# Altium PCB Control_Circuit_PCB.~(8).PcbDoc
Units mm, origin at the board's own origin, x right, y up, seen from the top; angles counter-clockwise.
Board outline 151.39 x 92 mm, 2 copper layers (Top Layer, Bottom Layer); 9 components, 6 nets, 22 pads, 1 vias.
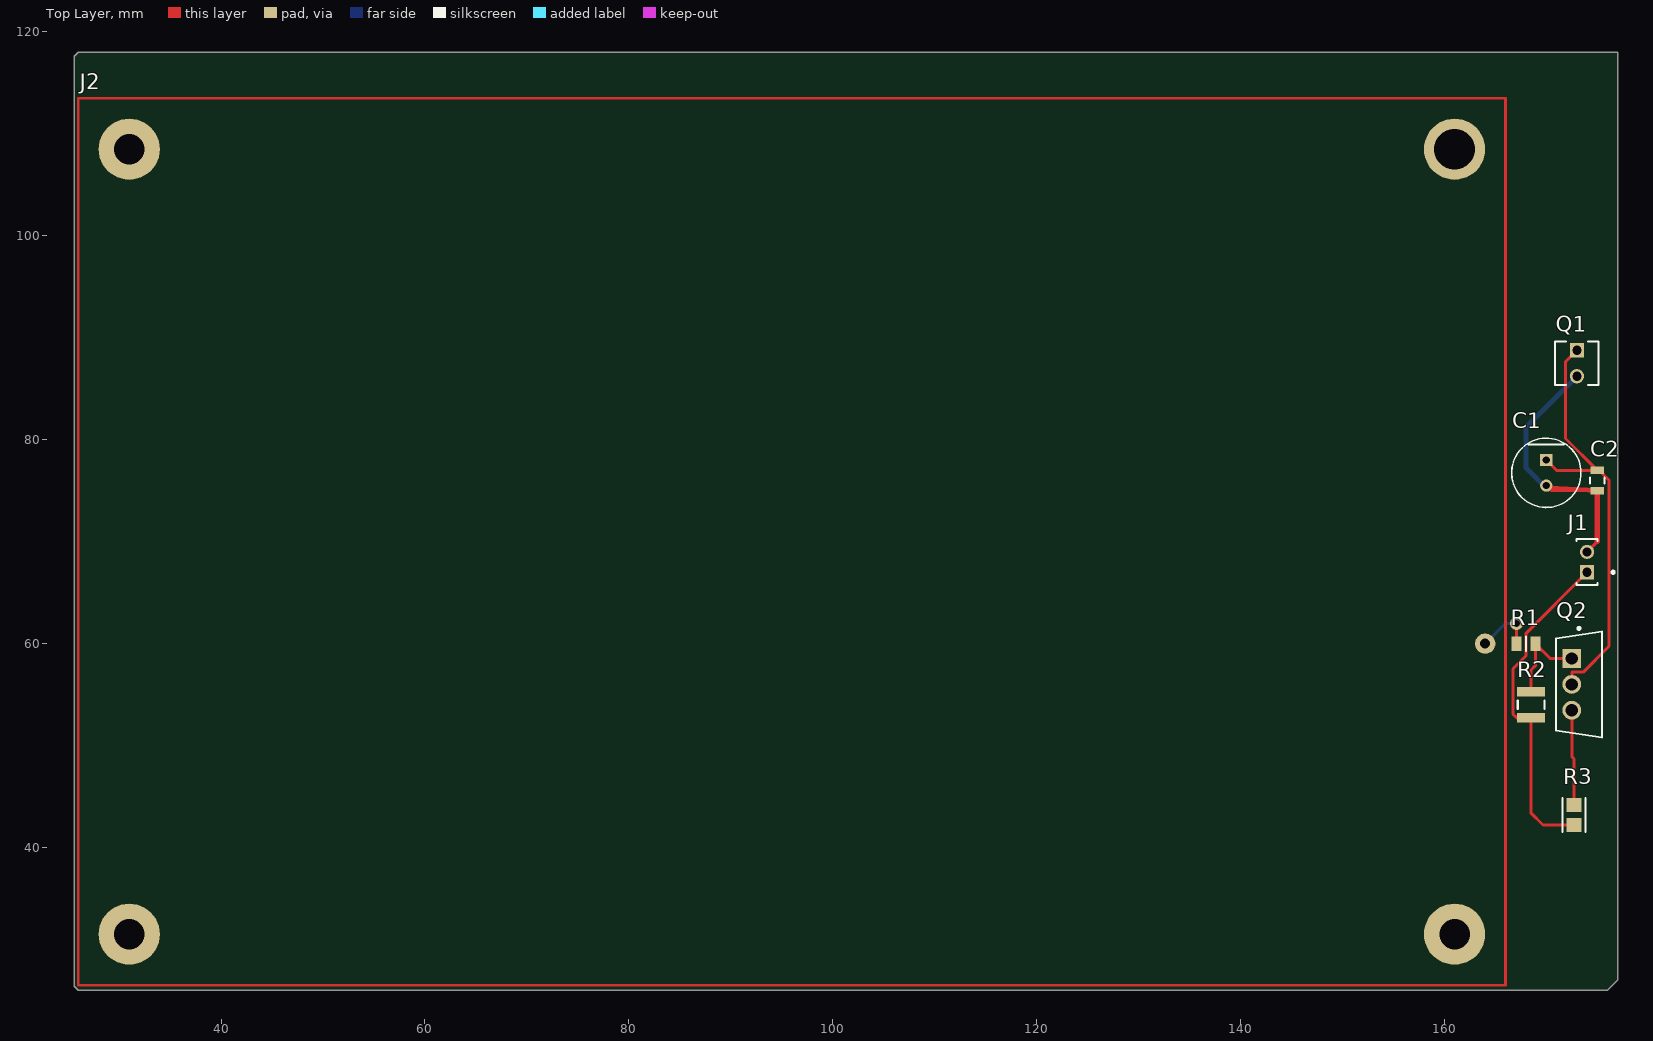
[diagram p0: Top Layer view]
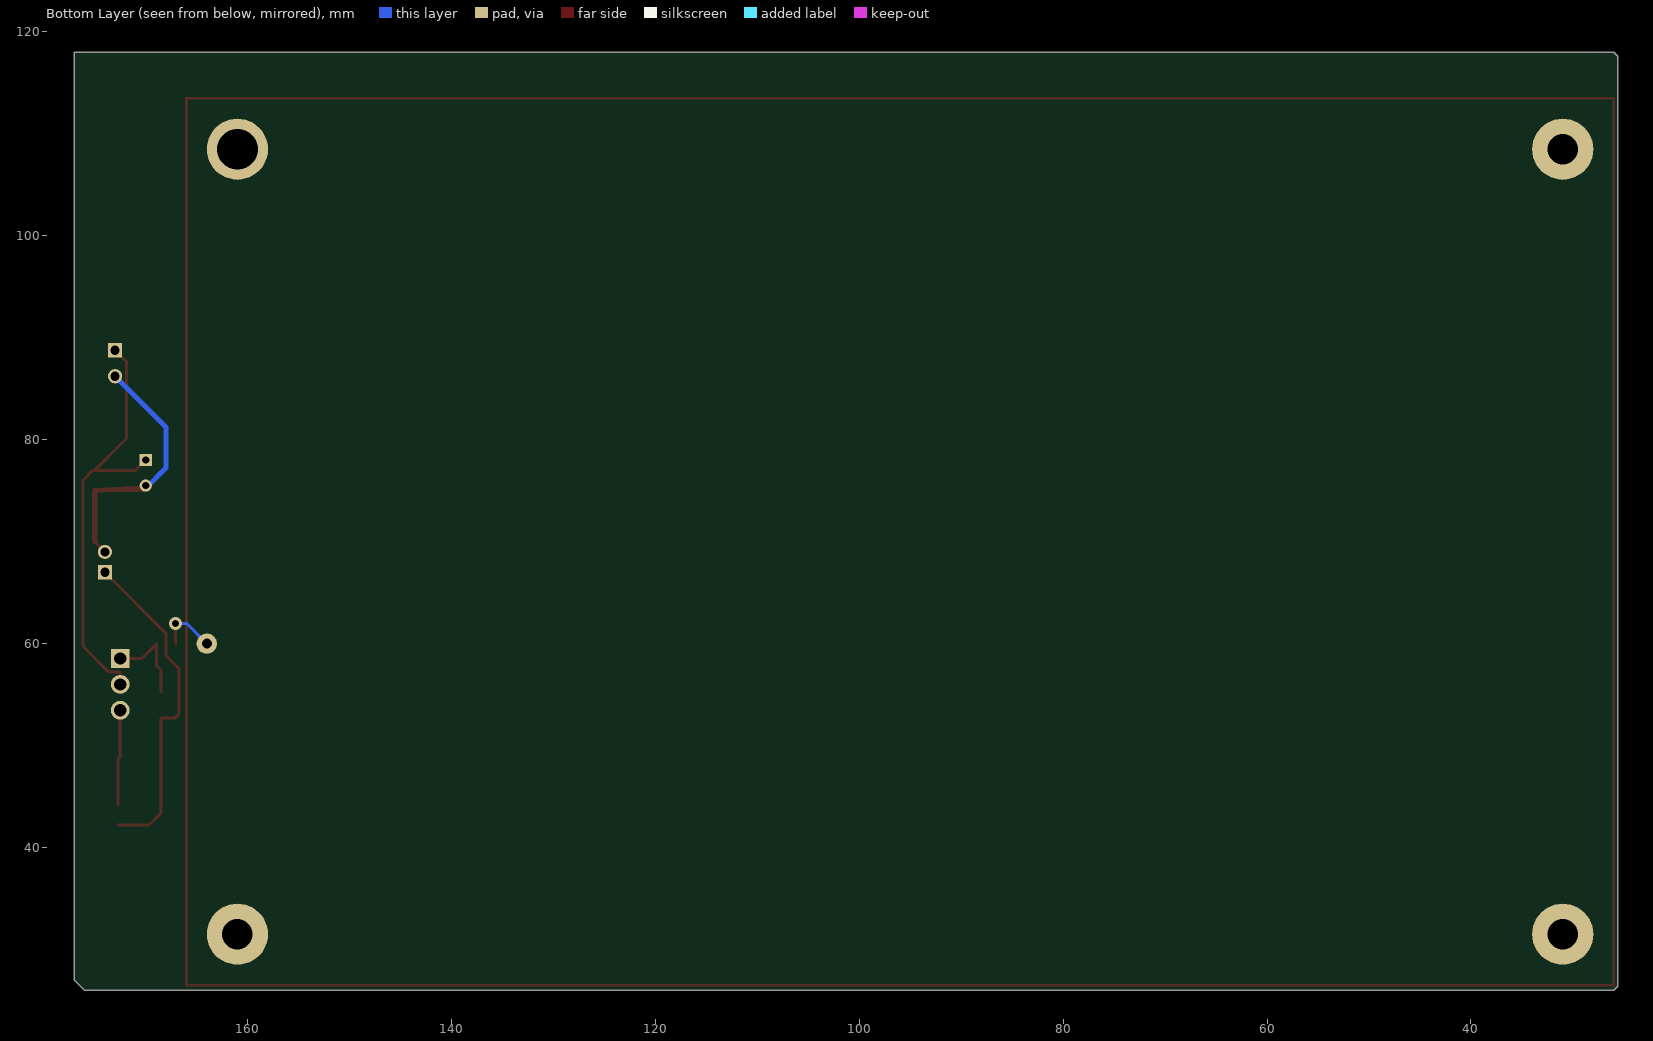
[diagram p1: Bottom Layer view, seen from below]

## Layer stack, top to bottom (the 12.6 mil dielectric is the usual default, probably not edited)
Top Solder: solder mask 0.0102, Solder Resist, Dk 3.5
Top Layer: signal copper 0.0356
Dielectric 1: dielectric 0.32, FR-4, Dk 4.8
Bottom Layer: signal copper 0.0356
Bottom Solder: solder mask 0.0102, Solder Resist, Dk 3.5

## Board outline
26,26 25.612,26.388 25.612,117.612 26,118 177,118 177,27 176,26

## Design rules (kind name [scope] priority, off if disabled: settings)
Clearance [All] p1: gap=0.254 ignorepadtopadclearanceinfootprint=FALSE
PolygonConnect [All] p1: connectstyle=Relief reliefconductorwidth=0.254 reliefentries=4 polygonreliefangle="90 Angle" airgapwidth=0.254
RoutingVias [All] p1: holewidth=0.711 width=1.27 viastyle="Through Hole" minholewidth=0.711 minwidth=1.27 maxholewidth=0.711 maxwidth=1.27
SolderMaskExpansion [All] p1: expansion=0 istentingtop=FALSE
SupplyNets "Schematic Supply Nets_1" [InNet('+5')] p1: voltage=0.000
SupplyNets "Schematic Supply Nets" [InNet('GND')] p2: voltage=0.000
Width [All] p1: maxlimit=0.5 minlimit=0.254 preferedwidth=0.3
30 further rules are at their usual default settings.

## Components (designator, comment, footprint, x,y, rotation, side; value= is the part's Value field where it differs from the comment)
C1 "100uF" FP-RAD-TH-D_6_3_0_5-L_11-MFG 170,76.75 r270 top
C2 "100nF" FP-GCE21B-0_3-MFG 175,76 r90 top
J1 "Power" FP-TMM-102-03-T-S-MFG 174,68 r90 top
J2 "PYNQZ2" PYNQZ2_board 96,70 r0 top
Q1 "LTR-4206" FP-LTR-4206-MFG 173,87.5 r270 top
Q2 "IRLZ44" FP-PG-TO220-3-MFG 173.205,56 r0 top
R1 "220" FP-MCU0805-IPC_B 168,60 r0 top
R2 "10k" FP-CRGCQ1210-IPC_C 168.5,54 r90 top value=10KΩ
R3 "3.3" FP-RMCF0805-IPC_A 172.72,43.18 r90 top

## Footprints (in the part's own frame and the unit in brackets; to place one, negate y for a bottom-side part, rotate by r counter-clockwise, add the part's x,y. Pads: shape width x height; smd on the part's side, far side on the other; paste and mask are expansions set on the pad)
FP-CRGCQ1210-IPC_C [mm]
  rect 0.958x2.706 smd paste+0 mask+0: 1(-1.277,0) 2(1.277,0)
  silkscreen extent -0.42,-1.3 0.42,1.3, body extent -1.86,-1.5 1.86,1.5, height 0.25
FP-GCE21B-0_3-MFG [mm]
  rect 0.7x1.3 smd paste+0 mask+0: 1(-1,0) 2(1,0)
  silkscreen extent -0.27,-0.73 0.27,0.73, body extent -1.45,-0.82 1.45,0.82, height 0.25
FP-LTR-4206-MFG [mm]
  rect 1.4x1.4 hole 0.9 paste-2539.97 mask+0: 1(-1.27,0)
  round 1.4 hole 0.9 paste-2539.97 mask+0: 2(1.27,0)
  silkscreen extent -2.13,-2.13 2.13,2.13, body extent -2.22,-2.22 2.22,2.22, height 0.25
FP-MCU0805-IPC_B [mm]
  rect 0.959x1.408 smd paste+0 mask+0: 1(-0.927,0) 2(0.927,0)
  silkscreen extent 0,-0.7 0,0.7, body extent -1.66,-0.95 1.66,0.95, height 0.25
FP-PG-TO220-3-MFG [mm]
  rect 1.85x1.85 hole 1.2 paste-2539.97 mask+0: 1(-0.705,2.54)
  round 1.85 hole 1.2 paste-2539.97 mask+0: 2(-0.705,0) 3(-0.705,-2.54)
  silkscreen extent -2.27,-5.2 2.28,5.62, body extent -2.37,-5.55 2.37,5.55, height 0.25
FP-RAD-TH-D_6_3_0_5-L_11-MFG [mm]
  rect 1.2x1.2 hole 0.7 paste-2539.97 mask+0: 1(-1.25,0)
  round 1.2 hole 0.7 paste-2539.97 mask+0: 2(1.25,0)
  silkscreen extent -3.4,-3.4 3.4,3.4, body extent -3.5,-3.5 3.5,3.5, height 0.25
FP-RMCF0805-IPC_A [mm]
  rect 1.355x1.462 smd paste+0 mask+0: 1(-0.976,0) 2(0.976,0)
  silkscreen extent -1.65,-1.13 1.65,1.13, body extent -2.15,-1.23 2.15,1.23, height 0.25
FP-TMM-102-03-T-S-MFG [mm]
  rect 1.39x1.39 hole 0.89 paste-2539.97 mask+0: 1(-1,0)
  round 1.39 hole 0.89 paste-2539.97 mask+0: 2(1,0)
  silkscreen extent -2.25,-2.68 2.25,1.02, body extent -2.1,-2.07 2.1,2.07, height 0.25
PYNQZ2_board [mm]
  round 6 hole 3: 0(-65,-38.5) 0(-65,38.5) 0(65,-38.5)
  round 6 hole 4: 0(65,38.5)
  round 2 hole 1: 1(68,-10)
  Top Layer lines w0.254: -70,-43.5 -70,43.5 70,43.5 70,-43.5 -70,-43.5

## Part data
C1: library part CMP-05427-000856-1, "Aluminum Electrolytic Capacitors (Radial Lead Type) 100uF ±20% 25V", Case/Package=Radial, ESR (Equivalent Series Resistance)=130mR, Max Operating Temperature=105°C, Min Operating Temperature=-40°C, Package Quantity=2000, Ripple Current=455mA, Tolerance=20%, Voltage Rating=25V
C2: library part CMP-06035-010744-1, "Ceramic Capacitor 100nF ±20% 100V X7R 0805"
J1: library part CMP-02766-001621-1, "CONN HEADER VERT 2POS 2MM", Color=Black, Max Current Rating=3.9A, Max Operating Temperature=105°C, Max Voltage Rating (AC)=500V, Min Operating Temperature=-55°C, Package Quantity=1
Q1: library part CMP-22030-000001-1, "SENSOR PHOTO 940NM TOP VIEW T1", Collector Emitter Breakdown Voltage=30V, Dark Current=0.1uA, Manufacturer=Lite-On, Max Collector Current=9.6mA, Power Dissipation=100mW, Temperature="-40°C to +85°C", Temperature Range High=+85°C, Temperature Range Low=-40°C
Q2: library part CMP-32901-000488-1, "MOSFET N-CH 55V 47A TO220AB", Case/Package=TO-220, Continuous Drain Current (ID)=47A, Drain to Source Breakdown Voltage=55V, Drain to Source Resistance=35mR, Gate to Source Voltage (Vgs)=16V, Input Capacitance=1.7nF, Max Operating Temperature=175°C, Max Power Dissipation=110W, Min Operating Temperature=-55°C, Threshold Voltage=2V
R1: library part CMP-02407-000312-1, "RES 1.05K OHM 0.5% 1/5W 0805", Case/Package=0805, Max Operating Temperature=125°C, Max Power Dissipation=125mW, Min Operating Temperature=-55°C, Package Quantity=5000, Resistance=220R, Temperature Coefficient=25ppm/°C, Tolerance=0.1%
R2: library part CMP-03211-005276-1, "CRGCQ1210 10KΩ 0.5W ±100ppm/°C 1% 200V", Ambient Temperature Range High=+70°C, Manufacturer="TE Connectivity", Manufacturer Part Number=CRGCQ1210F10K, Package=CRGCQ1210, Power Rating=0.5W, Resistance=10KΩ, Temperature="-55°C to +155°C", Temperature Coefficient=±100ppm/°C, Temperature Range High=+155°C, Temperature Range Low=-55°C, Tolerance=0.01, Voltage Rating=200V
R3: library part CMP-26527-003650-1, "3.3Ω ±5% 0.125W 0805 Thick Film Chip Resistor AEC-Q200 compliant", Case Code (Imperial)=0805, Case Code (Metric)=2012, Max Operating Temperature=155°C, Max Power Dissipation=125mW, Min Operating Temperature=-55°C, Resistance=3.3R, Resistor Type="Thick Film", Temperature Coefficient=200ppm/°C, Tolerance=5%

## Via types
v1: diameter 1.27, hole 0.711, Top Layer to Bottom Layer, 1 vias

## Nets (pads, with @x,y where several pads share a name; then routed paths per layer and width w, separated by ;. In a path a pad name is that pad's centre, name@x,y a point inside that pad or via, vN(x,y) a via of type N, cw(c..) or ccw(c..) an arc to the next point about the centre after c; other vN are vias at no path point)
+5: C1.2 C2.1 J1.2 Q1.2 | length 30.5
  Top Layer w0.3: C1.2 170.25,75.25 170.5,75 C2.1 ; J1.2 175,70
  Top Layer w0.5: C1.2@170,75.25 170.25,75.25 C2.1 175,70
  Bottom Layer w0.5: C1.2@170,75.25 168,77.25 168,81.23 Q1.2
GND: J1.1 R2.1 R3.1 | length 32.9
  Top Layer w0.3: R2.1 R2.1@168.478,52.723 ; R3.1 169.672,42.204 168.478,43.398 R2.1@168.478,52.723 ; J1.1 168.021,61.021 168.021,58.826 166.726,57.531 166.726,53.086 167.089,52.723 R2.1@168.478,52.723
NetC1_1: C1.1 C2.2 Q1.1 Q2.2 | length 42.7
  Top Layer w0.3: C1.1 171,77 C2.2 ; Q2.2 172.5,57.201 173.609,57.201 176.154,59.746 176.154,76.03 175.184,77 C2.2 ; Q1.1 171.882,87.652 171.882,80.118 C2.2
NetJ2_1: J2.1 R1.1 | length 5.9
  Top Layer w0.3: R1.1 v1(167.073,61.976)
  Bottom Layer w0.3: J2.1 165.976,61.976 v1(167.073,61.976)
NetQ2_1: Q2.1 R1.2 R2.2 | length 9.1
  Top Layer w0.3: R2.2 168.5,57.404 168.927,57.831 R1.2 170.387,58.54 Q2.1
NetQ2_3: Q2.3 R3.2 | length 9.4
  Top Layer w0.3: Q2.3 172.5,48.912 172.72,48.692 R3.2
pads on no net: J2.0

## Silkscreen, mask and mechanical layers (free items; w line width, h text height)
Mechanical 1:
  lines w0.254: 177,118 26,118 25.612,117.612 25.612,26.388 26,26 176,26 177,27 177,28 177,118 ; 177,118 177,118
